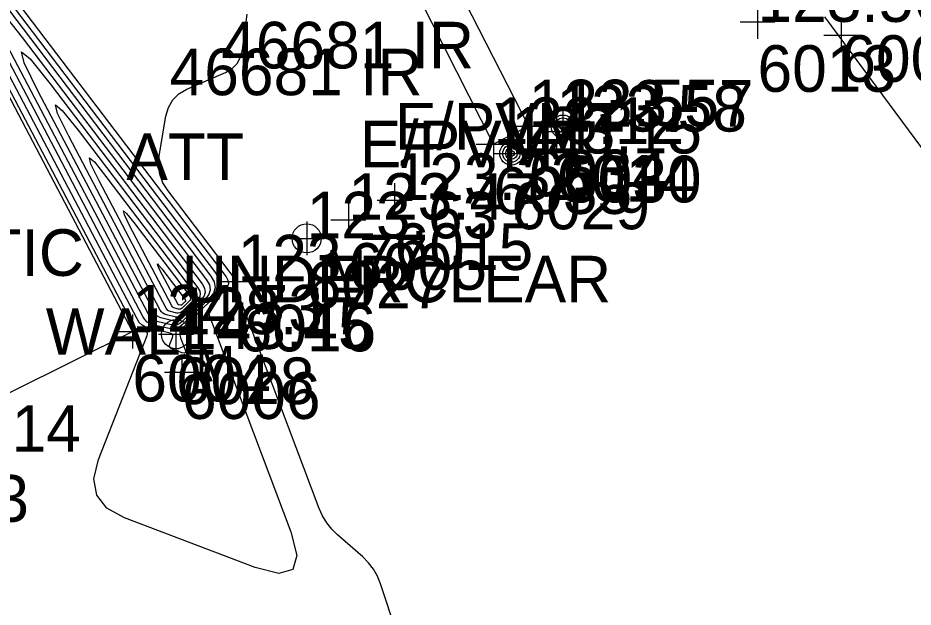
# Model space of a CAD drawing. Extents: x 13482745 to 13483091, y 311698 to 312158.
# Drawn here: x 13482915.9 to 13482977.4, y 311863.1 to 311903.6 of the extents above; entities that cross this region are included whole.
import ezdxf

# ---------------------------------------------------------------- set-up
doc = ezdxf.new("R2010")
doc.units = 0
for name, color, linetype in [('V-BLDG-OTLN', 7, 'Continuous'), ('V-PROP-MONM', 7, 'Continuous'), ('V-PVMT-ROAD', 7, 'Continuous'), ('V-PVMT-SPOT', 7, 'Continuous'), ('V-SITE-FEAT', 7, 'Continuous'), ('V-SITE-IDEN', 7, 'Continuous'), ('V-SITE-SPOT', 7, 'Continuous'), ('V-SURV-PNTS', 7, 'Continuous'), ('V-SURV-SPOT', 7, 'Continuous'), ('V-TOPO-LINE-IDEN', 7, 'Continuous'), ('V-TOPO-MAJR', 7, 'Continuous'), ('V-TOPO-MINR', 7, 'Continuous'), ('V-TOPO-SPOT', 7, 'Continuous')]:
    doc.layers.add(name, color=color, linetype=linetype)

msp = doc.modelspace()

# ---------------------------------------------------------------- linework, layer by layer
at = {"layer": 'V-BLDG-OTLN'}
msp.add_lwpolyline([(13482938.745, 311812.013), (13482914.39, 311859.782), (13482907.168, 311873.788), (13482923.791, 311882.044), (13482902.533, 311922.545), (13482900.37, 311926.805)], dxfattribs=at)
at = {"layer": 'V-PROP-MONM'}
for centre, radius in [((13482953.369, 311896.101), 0.8), ((13482953.369, 311896.101), 0.6), ((13482953.369, 311896.101), 0.4), ((13482953.369, 311896.101), 0.2), ((13482949.827, 311894.263), 0.8), ((13482949.827, 311894.263), 0.6), ((13482949.827, 311894.263), 0.4), ((13482949.827, 311894.263), 0.2)]:
    msp.add_circle(centre, radius, dxfattribs=at)
at = {"layer": 'V-PVMT-ROAD'}
msp.add_lwpolyline([(13482951.007, 311896.128), (13482948.602, 311894.913), (13482925.919, 311939.656), (13482928.099, 311940.841), (13482951.007, 311896.128)], dxfattribs=at)
at = {"layer": 'V-PVMT-SPOT'}
for p, q in [((13482951.007, 311897.288), (13482951.007, 311894.968)), ((13482948.602, 311896.073), (13482948.602, 311893.753)), ((13482949.807, 311896.128), (13482952.207, 311896.128)), ((13482947.402, 311894.913), (13482949.802, 311894.913))]:
    msp.add_line(p, q, dxfattribs=at)
at = {"layer": 'V-SITE-FEAT'}
for centre in [(13482935.767, 311888.437), (13482926.788, 311881.861)]:
    msp.add_circle(centre, 1, dxfattribs=at)
at = {"layer": 'V-SITE-SPOT'}
for p, q in [((13482972.488, 311903.539), (13482972.488, 311901.219)), ((13482971.288, 311902.379), (13482973.688, 311902.379)), ((13482935.767, 311889.597), (13482935.767, 311887.277)), ((13482934.567, 311888.437), (13482936.967, 311888.437)), ((13482923.791, 311883.204), (13482923.791, 311880.884)), ((13482926.788, 311883.021), (13482926.788, 311880.701)), ((13482922.591, 311882.044), (13482924.991, 311882.044)), ((13482925.588, 311881.861), (13482927.988, 311881.861)), ((13482927.199, 311880.404), (13482927.199, 311878.084)), ((13482925.999, 311879.244), (13482928.399, 311879.244))]:
    msp.add_line(p, q, dxfattribs=at)
at = {"layer": 'V-SURV-SPOT'}
for p, q in [((13482953.369, 311897.261), (13482953.369, 311894.941)), ((13482952.169, 311896.101), (13482954.569, 311896.101)), ((13482949.827, 311895.423), (13482949.827, 311893.103)), ((13482948.627, 311894.263), (13482951.027, 311894.263))]:
    msp.add_line(p, q, dxfattribs=at)
at = {"layer": 'V-TOPO-MAJR'}
for points in [[(13482929.411, 311885.446), (13482929.469, 311885.051), (13482929.354, 311884.669), (13482929.068, 311884.3), (13482927.221, 311882.496), (13482927.02, 311882.34), (13482926.803, 311882.246), (13482926.568, 311882.214), (13482926.316, 311882.243), (13482925.273, 311882.486), (13482925.029, 311882.569), (13482924.819, 311882.696), (13482924.644, 311882.866), (13482924.502, 311883.081), (13482913.153, 311904.654), (13482911.776, 311907.456), (13482911.51, 311908.514), (13482912.356, 311907.827), (13482914.315, 311905.395), (13482929.183, 311885.853)], [(13482927.766, 311884.403), (13482927.781, 311884.302), (13482927.752, 311884.204), (13482927.678, 311884.109), (13482927.204, 311883.647), (13482927.153, 311883.607), (13482927.097, 311883.583), (13482927.037, 311883.574), (13482926.972, 311883.582), (13482926.705, 311883.644), (13482926.642, 311883.665), (13482926.589, 311883.698), (13482926.543, 311883.742), (13482926.507, 311883.797), (13482923.596, 311889.33), (13482923.243, 311890.048), (13482923.175, 311890.319), (13482923.392, 311890.143), (13482923.894, 311889.519), (13482927.708, 311884.508)]]:
    msp.add_lwpolyline(points, close=True, dxfattribs=at)
at = {"layer": 'V-TOPO-MINR'}
for points in [[(13482910.483, 311911.745), (13482930.227, 311885.794), (13482930.359, 311885.559), (13482930.392, 311885.333), (13482930.326, 311885.113), (13482930.161, 311884.901), (13482929.306, 311884.066), (13482929.132, 311883.848), (13482929.038, 311883.613), (13482929.024, 311883.36), (13482929.09, 311883.089), (13482934.679, 311868.306), (13482935.087, 311866.666), (13482934.812, 311865.71), (13482933.855, 311865.437), (13482932.216, 311865.847), (13482923.248, 311869.255), (13482922.043, 311869.921), (13482921.346, 311870.812), (13482921.156, 311871.927), (13482921.473, 311873.266), (13482924.817, 311881.767), (13482924.839, 311881.862), (13482924.824, 311881.937), (13482924.771, 311881.992), (13482924.68, 311882.027), (13482924.242, 311882.129), (13482924.14, 311882.164), (13482924.052, 311882.217), (13482923.978, 311882.289), (13482923.919, 311882.379), (13482908.975, 311910.784)], [(13482912.399, 311908.57), (13482929.514, 311886.074), (13482929.763, 311885.63), (13482929.826, 311885.199), (13482929.701, 311884.783), (13482929.389, 311884.38), (13482927.248, 311882.29), (13482927.129, 311882.14), (13482927.064, 311881.979), (13482927.054, 311881.805), (13482927.1, 311881.619), (13482927.416, 311880.784), (13482927.448, 311880.653), (13482927.426, 311880.577), (13482927.35, 311880.556), (13482927.22, 311880.588), (13482926.507, 311880.859), (13482926.411, 311880.912), (13482926.356, 311880.983), (13482926.341, 311881.071), (13482926.366, 311881.178), (13482926.548, 311881.639), (13482926.572, 311881.744), (13482926.555, 311881.827), (13482926.497, 311881.887), (13482926.397, 311881.926), (13482924.95, 311882.263), (13482924.687, 311882.352), (13482924.461, 311882.489), (13482924.271, 311882.673), (13482924.118, 311882.905), (13482911.064, 311907.719)], [(13482945.231, 311851.464), (13482940.842, 311864.729), (13482940.63, 311865.252), (13482940.356, 311865.734), (13482940.018, 311866.173), (13482939.618, 311866.571), (13482937.89, 311868.079), (13482937.486, 311868.476), (13482937.14, 311868.913), (13482936.852, 311869.389), (13482936.62, 311869.906), (13482930.825, 311885.237), (13482930.818, 311885.264), (13482930.819, 311885.29), (13482930.829, 311885.314), (13482930.847, 311885.336), (13482930.934, 311885.421), (13482930.951, 311885.443), (13482930.957, 311885.466), (13482930.954, 311885.489), (13482930.941, 311885.513), (13482926.242, 311891.689), (13482925.896, 311892.246), (13482925.681, 311892.835), (13482925.597, 311893.457), (13482925.644, 311894.111), (13482926.098, 311896.817), (13482926.272, 311897.426), (13482926.57, 311897.937), (13482926.994, 311898.351), (13482927.543, 311898.667), (13482930.187, 311899.821), (13482930.644, 311900.085), (13482930.991, 311900.433), (13482931.228, 311900.863), (13482931.354, 311901.377), (13482931.668, 311903.823)], [(13482971.343, 311903.645), (13482980.61, 311891.135)]]:
    msp.add_lwpolyline(points, dxfattribs=at)
for points in [[(13482929.082, 311885.237), (13482929.131, 311884.901), (13482929.034, 311884.576), (13482928.79, 311884.262), (13482927.217, 311882.726), (13482927.047, 311882.593), (13482926.862, 311882.513), (13482926.662, 311882.486), (13482926.447, 311882.511), (13482925.559, 311882.718), (13482925.352, 311882.788), (13482925.173, 311882.896), (13482925.024, 311883.041), (13482924.903, 311883.224), (13482915.241, 311901.589), (13482914.069, 311903.975), (13482913.843, 311904.875), (13482914.564, 311904.29), (13482916.231, 311902.22), (13482928.888, 311885.584)], [(13482928.753, 311885.029), (13482928.794, 311884.751), (13482928.713, 311884.483), (13482928.512, 311884.224), (13482927.214, 311882.956), (13482927.074, 311882.847), (13482926.921, 311882.781), (13482926.756, 311882.758), (13482926.579, 311882.779), (13482925.846, 311882.949), (13482925.674, 311883.007), (13482925.527, 311883.097), (13482925.403, 311883.217), (13482925.304, 311883.368), (13482917.33, 311898.524), (13482916.363, 311900.493), (13482916.176, 311901.236), (13482916.771, 311900.753), (13482918.147, 311899.045), (13482928.593, 311885.315)], [(13482928.424, 311884.82), (13482928.456, 311884.602), (13482928.393, 311884.39), (13482928.234, 311884.186), (13482927.211, 311883.187), (13482927.1, 311883.1), (13482926.98, 311883.048), (13482926.849, 311883.03), (13482926.71, 311883.047), (13482926.132, 311883.181), (13482925.997, 311883.227), (13482925.881, 311883.297), (13482925.783, 311883.392), (13482925.705, 311883.511), (13482919.419, 311895.459), (13482918.656, 311897.011), (13482918.509, 311897.597), (13482918.978, 311897.217), (13482920.062, 311895.87), (13482928.298, 311885.046)], [(13482928.095, 311884.612), (13482928.118, 311884.452), (13482928.072, 311884.297), (13482927.956, 311884.147), (13482927.208, 311883.417), (13482927.127, 311883.353), (13482927.038, 311883.315), (13482926.943, 311883.302), (13482926.841, 311883.314), (13482926.418, 311883.413), (13482926.32, 311883.446), (13482926.235, 311883.497), (13482926.163, 311883.567), (13482926.106, 311883.654), (13482921.508, 311892.395), (13482920.95, 311893.53), (13482920.842, 311893.958), (13482921.185, 311893.68), (13482921.978, 311892.694), (13482928.003, 311884.777)], [(13482927.437, 311884.195), (13482927.443, 311884.152), (13482927.431, 311884.111), (13482927.4, 311884.071), (13482927.201, 311883.877), (13482927.18, 311883.86), (13482927.156, 311883.85), (13482927.131, 311883.846), (13482927.104, 311883.85), (13482926.991, 311883.876), (13482926.965, 311883.885), (13482926.942, 311883.898), (13482926.923, 311883.917), (13482926.908, 311883.94), (13482925.685, 311886.265), (13482925.537, 311886.567), (13482925.508, 311886.681), (13482925.599, 311886.607), (13482925.81, 311886.344), (13482927.413, 311884.239)]]:
    msp.add_lwpolyline(points, close=True, dxfattribs=at)
at = {"layer": 'V-TOPO-SPOT'}
for p, q in [((13482966.73, 311904.455), (13482966.73, 311902.135)), ((13482965.53, 311903.295), (13482967.93, 311903.295)), ((13482952.916, 311896.926), (13482952.916, 311894.606)), ((13482951.716, 311895.766), (13482954.116, 311895.766)), ((13482941.807, 311892.226), (13482941.807, 311889.906)), ((13482938.628, 311890.872), (13482938.628, 311888.552)), ((13482940.607, 311891.066), (13482943.007, 311891.066)), ((13482937.428, 311889.712), (13482939.828, 311889.712)), ((13482931.022, 311886.641), (13482931.022, 311884.321)), ((13482929.822, 311885.481), (13482932.222, 311885.481))]:
    msp.add_line(p, q, dxfattribs=at)

# ---------------------------------------------------------------- texts
at = {"layer": 'V-PROP-MONM'}
for p in [(13482929.893, 311900.101), (13482926.351, 311898.263)]:
    msp.add_text('46681 IR', height=3.2, dxfattribs=at).set_placement(p)
at = {"layer": 'V-PVMT-SPOT'}
for s, p in [('123.55', (13482951.007, 311896.128)), ('123.12', (13482948.602, 311894.913))]:
    msp.add_text(s, height=3.2, dxfattribs=at).set_placement(p)
at = {"layer": 'V-SITE-FEAT'}
for p in [(13482937.127, 311885.237), (13482928.148, 311878.661)]:
    msp.add_text('M', height=2.4, rotation=360, dxfattribs=at).set_placement(p)
at = {"layer": 'V-SITE-IDEN'}
for s, p in [('ATT', (13482923.376, 311892.437)), ('FIBER-OPTIC', (13482893.36, 311885.861)), ('UNDERCLEAR', (13482927.199, 311884.044))]:
    msp.add_text(s, height=3.2, dxfattribs=at).set_placement(p)
at = {"layer": 'V-SITE-SPOT'}
for s, p in [('123.63', (13482935.767, 311888.437)), ('124.73', (13482923.791, 311882.044)), ('128.17', (13482926.788, 311881.861)), ('143.45', (13482927.199, 311880.844)), ('125.14', (13482907.168, 311873.788))]:
    msp.add_text(s, height=3.2, dxfattribs=at).set_placement(p)
at = {"layer": 'V-SURV-PNTS'}
for s, p in [('6007', (13482972.488, 311899.179)), ('6013', (13482966.73, 311898.495)), ('6034', (13482951.007, 311891.328)), ('6014', (13482952.916, 311890.966)), ('6030', (13482953.369, 311890.901)), ('6035', (13482948.602, 311890.113)), ('6029', (13482949.827, 311889.063)), ('6015', (13482941.807, 311886.266)), ('6005', (13482938.628, 311884.912)), ('6027', (13482935.767, 311883.637)), ('6016', (13482931.022, 311880.681)), ('6004', (13482923.791, 311877.244)), ('6028', (13482926.788, 311877.061)), ('6006', (13482927.199, 311876.044)), ('6003', (13482907.168, 311868.988))]:
    msp.add_text(s, height=3.2, dxfattribs=at).set_placement(p)
at = {"layer": 'V-SURV-SPOT'}
for s, p in [('123.57', (13482953.369, 311896.101)), ('123.15', (13482949.827, 311894.263))]:
    msp.add_text(s, height=3.2, dxfattribs=at).set_placement(p)
at = {"layer": 'V-TOPO-LINE-IDEN'}
for s, p in [('E/PVMT', (13482941.823, 311894.528)), ('E/PVMT', (13482939.418, 311893.313)), ('WALL', (13482917.845, 311880.444))]:
    msp.add_text(s, height=3.2, dxfattribs=at).set_placement(p)
at = {"layer": 'V-TOPO-SPOT'}
for s, p in [('123.56', (13482966.73, 311903.295)), ('123.58', (13482952.916, 311895.766)), ('123.32', (13482941.807, 311891.066)), ('123.47', (13482938.628, 311889.712)), ('123.77', (13482931.022, 311885.481))]:
    msp.add_text(s, height=3.2, dxfattribs=at).set_placement(p)

doc.saveas('drawing.dxf')
